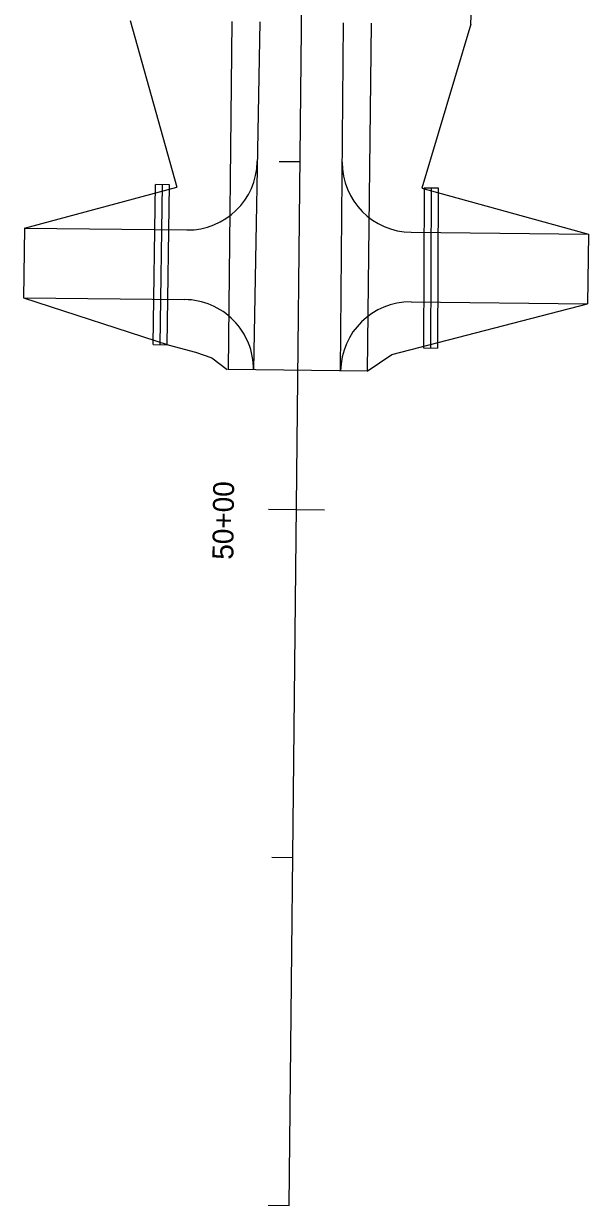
# Model space of a CAD drawing. Extents: x 1611108 to 1749517, y 619561 to 797725.
# Drawn here: x 1728230.7 to 1728392.9, y 771056.8 to 771396.4 of the extents above; entities that cross this region are included whole.
import ezdxf

# ---------------------------------------------------------------- set-up
doc = ezdxf.new("R2010")
doc.units = 0
for name, color, linetype in [('R_Drainage', 7, 'Continuous'), ('R_Horz Alg', 7, 'Continuous'), ('R_Horz Alg Stationing_Side Road', 7, 'Continuous'), ('R_Proposed Const Limits', 7, 'Continuous'), ('R_Proposed Road', 7, 'Continuous')]:
    doc.layers.add(name, color=color, linetype=linetype)

msp = doc.modelspace()

# ---------------------------------------------------------------- linework, layer by layer
at = {"layer": 'R_Drainage'}
for p, q in [((1728267.9, 771304.19), (1728268.59, 771350.18)), ((1728272.59, 771350.12), (1728268.59, 771350.18)), ((1728269.9, 771304.16), (1728270.59, 771350.15)), ((1728271.9, 771304.13), (1728272.59, 771350.12)), ((1728345.74, 771349.24), (1728345.53, 771303.24)), ((1728345.74, 771349.24), (1728349.74, 771349.22)), ((1728347.74, 771349.23), (1728347.53, 771303.23)), ((1728349.74, 771349.22), (1728349.53, 771303.22)), ((1728267.9, 771304.19), (1728271.9, 771304.13)), ((1728345.53, 771303.24), (1728349.53, 771303.22))]:
    msp.add_line(p, q, dxfattribs=at)
at = {"layer": 'R_Horz Alg'}
msp.add_line((1728306.95, 771056.83), (1728332.15, 773463.77), dxfattribs=at)
at = {"layer": 'R_Horz Alg Stationing_Side Road'}
for points in [[(1728304.09, 771356.87), (1728310.09, 771356.81)], [(1728301.04, 771256.9), (1728317.04, 771256.73)], [(1728301.99, 771156.88), (1728307.99, 771156.82)], [(1728300.95, 771056.89), (1728306.95, 771056.83)]]:
    msp.add_lwpolyline(points, dxfattribs=at)
at = {"layer": 'R_Proposed Const Limits'}
for p, q in [((1728261.27, 771397.32), (1728274.69, 771349.47)), ((1728230.88, 771337.64), (1728274.69, 771349.47)), ((1728345.02, 771349.16), (1728392.87, 771335.94)), ((1728230.67, 771317.64), (1728272.45, 771304.06))]:
    msp.add_line(p, q, dxfattribs=at)
for points in [[(1728359.08, 771396.3), (1728359.47, 771406.29)], [(1728359.08, 771396.3), (1728345.02, 771349.16)], [(1728329.34, 771296.6), (1728336.41, 771301.32), (1728392.66, 771315.94)], [(1728272.45, 771304.06), (1728280.03, 771302), (1728284.76, 771300.41), (1728289.1, 771297.03)]]:
    msp.add_lwpolyline(points, dxfattribs=at)
at = {"layer": 'R_Proposed Road'}
for p, q in [((1728290.51, 771397.02), (1728289.39, 771297.02)), ((1728298.51, 771396.93), (1728296.7, 771296.95)), ((1728321.73, 771296.68), (1728322.51, 771396.68)), ((1728330.51, 771396.6), (1728329.34, 771296.6)), ((1728230.88, 771337.64), (1728230.67, 771317.64)), ((1728230.88, 771337.64), (1728277.58, 771337.15)), ((1728341.98, 771336.47), (1728392.87, 771335.94)), ((1728392.87, 771335.94), (1728392.66, 771315.94)), ((1728230.67, 771317.64), (1728276.91, 771317.15)), ((1728341.94, 771316.47), (1728392.66, 771315.94)), ((1728329.34, 771296.6), (1728289.39, 771297.02))]:
    msp.add_line(p, q, dxfattribs=at)
for centre, start, end in [((1728277.79, 771357.15), 269.4, 358.966), ((1728342.19, 771356.47), 179.5543, 269.4), ((1728276.7, 771297.15), 359.4, 89.4), ((1728341.73, 771296.47), 89.4, 179.4)]:
    msp.add_arc(centre, 20, start, end, dxfattribs=at)

# ---------------------------------------------------------------- texts
at = {"layer": 'R_Horz Alg Stationing_Side Road'}
msp.add_text('50+00', height=6, rotation=89.4, dxfattribs=at).set_placement((1728290.89, 771242.36))

doc.saveas('drawing.dxf')
